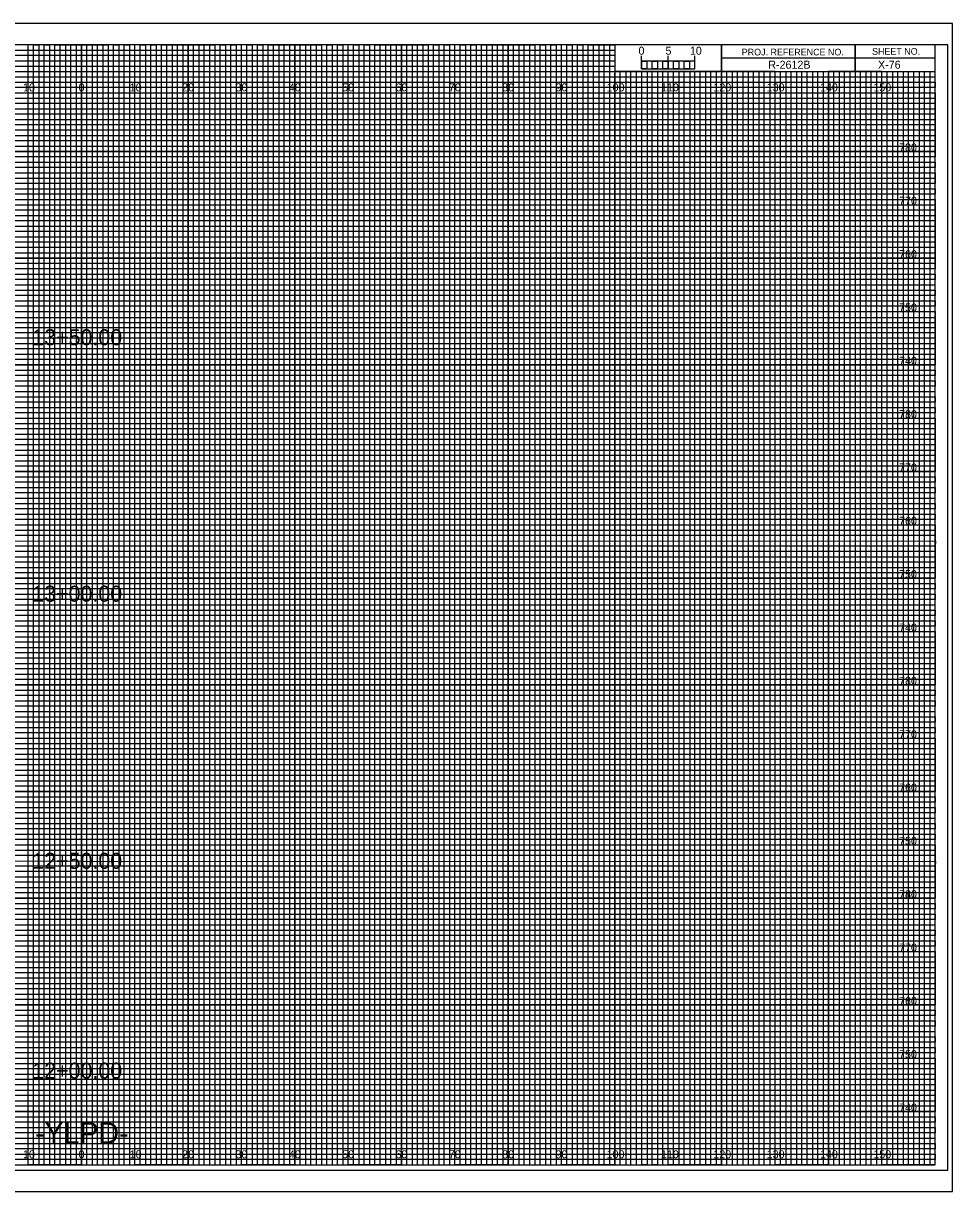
# Model space of a CAD drawing. Extents: x -13 to 323, y 215 to 434.
# Drawn here: x 149.1 to 323.3, y 215 to 434 of the extents above; entities that cross this region are included whole.
import ezdxf

# ---------------------------------------------------------------- set-up
doc = ezdxf.new("R2010")
doc.units = 0
for name, color, linetype in [('Prop XS Alignment Label', 7, 'Continuous'), ('Prop XS Bar Scale Labels', 7, 'Continuous'), ('Prop XS Elevation Labels', 7, 'Continuous'), ('Prop XS Offset Labels', 7, 'Continuous'), ('Prop XS Project Number', 7, 'Continuous'), ('Prop XS Sheet Number', 7, 'Continuous'), ('Prop XS Station Labels', 7, 'Continuous'), ('Sheet Cross Section CELL', 7, 'Continuous'), ('Sheet Cross Section Grid Major CELL', 7, 'Continuous'), ('Sheet Cross Section Grid Middle CELL', 7, 'Continuous'), ('Sheet Cross Section Grid Minor 1 CELL', 7, 'Continuous'), ('Sheet Cross Section Grid Minor 2 CELL', 7, 'Continuous'), ('Sheet Cross Section Scale CELL', 7, 'Continuous'), ('Sheet Cutting Line CELL', 7, 'Continuous'), ('Sheet DOT Grid CELL', 7, 'Continuous'), ('Sheet Plot Border Inside CELL', 7, 'Continuous'), ('Sheet Plot Border Outside CELL', 7, 'Continuous')]:
    doc.layers.add(name, color=color, linetype=linetype)

msp = doc.modelspace()

# ---------------------------------------------------------------- linework, layer by layer
at = {"layer": 'Sheet Cross Section CELL'}
for p, q in [((305, 430), (305, 425)), ((305, 425), (305, 430)), ((280, 427.5), (280, 425)), ((320, 427.49), (280, 427.49)), ((280, 425), (320, 425))]:
    msp.add_line(p, q, dxfattribs=at)
for points in [[(320, 430), (0, 430), (0, 220), (320, 220)], [(280, 430), (260, 430), (260, 425.03), (280, 425.03)], [(320, 430), (280, 430), (280, 425), (320, 425)]]:
    msp.add_lwpolyline(points, close=True, dxfattribs=at)
at = {"layer": 'Sheet Cross Section Grid Major CELL'}
for p, q in [((150, 430), (140, 430)), ((150, 220), (150, 430)), ((170, 430), (160, 430)), ((160, 430), (160, 220)), ((170, 220), (170, 430)), ((190, 430), (180, 430)), ((180, 430), (180, 220)), ((190, 220), (190, 430)), ((210, 430), (200, 430)), ((200, 430), (200, 220)), ((210, 220), (210, 430)), ((230, 430), (220, 430)), ((220, 430), (220, 220)), ((230, 220), (230, 430)), ((250, 430), (240, 430)), ((240, 430), (240, 220)), ((250, 220), (250, 430)), ((260, 430), (260, 220)), ((270, 220), (270, 425)), ((290, 425), (280, 425)), ((280, 425), (280, 220)), ((290, 220), (290, 425)), ((310, 425), (300, 425)), ((300, 425), (300, 220)), ((310, 220), (310, 425)), ((160, 220), (150, 220)), ((180, 220), (170, 220)), ((200, 220), (190, 220)), ((220, 220), (210, 220)), ((240, 220), (230, 220)), ((260, 220), (250, 220)), ((280, 220), (270, 220)), ((300, 220), (290, 220)), ((320, 220), (310, 220)), ((320, 220), (320, 220))]:
    msp.add_line(p, q, dxfattribs=at)
for points in [[(0, 420), (320, 420), (320, 410), (0, 410)], [(0, 400), (320, 400), (320, 390), (0, 390)], [(0, 380), (320, 380), (320, 370), (0, 370)], [(0, 360), (320, 360), (320, 350), (0, 350)], [(0, 340), (320, 340), (320, 330), (0, 330)], [(0, 320), (320, 320), (320, 310), (0, 310)], [(0, 300), (320, 300), (320, 290), (0, 290)], [(0, 280), (320, 280), (320, 270), (0, 270)], [(0, 260), (320, 260), (320, 250), (0, 250)], [(0, 240), (320, 240), (320, 230), (0, 230)]]:
    msp.add_lwpolyline(points, dxfattribs=at)
at = {"layer": 'Sheet Cross Section Grid Middle CELL'}
for points in [[(145, 220), (155, 220), (155, 430), (165, 430), (165, 220), (175, 220), (175, 430), (185, 430), (185, 220), (195, 220), (195, 430), (205, 430), (205, 220), (215, 220), (215, 430), (225, 430), (225, 220), (235, 220), (235, 430), (245, 430), (245, 220), (255, 220), (255, 430), (259.93, 430), (260, 430), (260, 425), (264.99, 425), (264.99, 220), (275, 220), (275, 425), (285, 425), (285, 220), (295, 220), (295, 425), (305, 425), (305, 220), (315, 220), (315, 425)], [(0, 425), (275, 425)], [(0, 405), (320, 405), (320, 415), (0, 415)], [(0, 385), (320, 385), (320, 395), (0, 395)], [(0, 365), (320, 365), (320, 375), (0, 375)], [(0, 345), (320, 345), (320, 355), (0, 355)], [(0, 325), (320, 325), (320, 335), (0, 335)], [(0, 305), (320, 305), (320, 315), (0, 315)], [(0, 285), (320, 285), (320, 295), (0, 295)], [(0, 265), (320, 265), (320, 275), (0, 275)], [(0, 245), (320, 245), (320, 255), (0, 255)], [(0, 225), (320, 225), (320, 235), (0, 235)]]:
    msp.add_lwpolyline(points, dxfattribs=at)
at = {"layer": 'Sheet Cross Section Grid Minor 1 CELL'}
for p, q in [((0, 429), (260, 429)), ((260, 427.98), (0, 427.98)), ((260, 429), (260, 427.98)), ((0, 427), (260, 427)), ((260, 425.89), (0, 425.89)), ((260, 427), (260, 425.89)), ((0, 424), (320, 424))]:
    msp.add_line(p, q, dxfattribs=at)
for points in [[(0, 423), (270, 423), (320, 423), (320, 422), (0, 422)], [(0, 421), (320, 421), (320, 419), (0, 419)], [(0, 418), (320, 418), (320, 417), (0, 416.98)], [(0, 416), (320, 416), (320, 414), (0, 414)], [(0, 413), (320, 413), (320, 412), (0, 412)], [(0, 411), (320, 411), (320, 409), (0, 409)], [(0, 408), (320, 408), (320, 407), (0, 407)], [(0, 406), (320, 406), (320, 404), (0, 404)], [(0, 403), (320, 403), (320, 402), (0, 402)], [(0, 401), (320, 401), (320, 399), (0, 399)], [(0, 398), (320, 398), (320, 397), (0, 397)], [(0, 396), (320, 396), (320, 393.95), (320, 393), (320, 392), (0, 392)], [(0, 394), (320, 394), (320, 393), (0, 393)], [(0, 391), (320, 391), (320, 389), (0, 389.03)], [(0, 389.03), (320, 389), (320, 388), (0, 388)], [(0, 387), (320, 387), (320, 386), (0, 386)], [(0, 384), (320, 384), (320, 383), (0, 383)], [(0, 382), (320, 382), (320, 381), (0, 381)], [(-0.07, 378.89), (320, 378.89), (320, 377.88), (-0.07, 377.88)], [(0, 377), (320, 377), (320, 376), (0, 376)], [(0, 374), (320, 374), (320, 373), (0, 373)], [(0, 372), (320, 372), (320, 371), (0, 371)], [(0, 369), (320, 369), (320, 368), (0, 368)], [(0, 367), (320, 367), (320, 366), (0, 366)], [(0, 364), (320, 364), (320, 363), (0, 363)], [(0, 362), (320, 362), (320, 361), (0, 361)], [(0, 359), (320, 359), (319.99, 357.98), (0, 358)], [(0, 357), (320, 357), (320, 356), (0, 356)], [(0, 354), (320, 354), (320, 353), (0, 353)], [(0, 352), (320, 352), (320, 351), (0, 351)], [(0, 349), (320, 349), (320, 348), (0, 348)], [(0, 347), (320, 347), (320, 346), (0, 346)], [(0, 344), (320, 344), (320, 343), (0, 343)], [(0, 342), (320, 342), (320, 341), (0, 341)], [(0, 339), (320, 339), (320, 338), (0, 338)], [(0, 336.99), (320.07, 336.91), (320, 336), (0, 336)], [(0, 334), (320, 334), (320, 333), (0, 333)], [(0, 332), (320, 332), (320, 331), (0, 331)], [(0, 329), (320, 329), (320, 328), (0, 328)], [(0, 327), (320, 327), (320, 326), (0, 326)], [(0, 324), (320, 324), (320, 323), (0, 323)], [(0, 322), (320, 322), (320, 321), (0, 321)], [(0, 319), (320, 319), (320, 318), (0, 318)], [(0, 317), (320, 317), (320, 316), (0, 316)], [(0, 314), (320, 314), (320, 313), (0, 313)], [(0, 312), (320, 312), (320, 311), (0, 311)], [(0, 309), (320, 309), (320, 308), (0, 308)], [(0, 307), (320, 307), (320, 306), (0, 306)], [(0, 304), (320, 304), (320, 303), (0, 303)], [(0, 302), (320, 302), (320, 301), (0, 301)], [(0, 299), (320, 299), (319.99, 297.98), (0, 298)], [(0, 297), (320, 297), (320, 296), (0, 296)], [(0, 294), (320, 294), (320, 293), (0, 293)], [(0, 292), (320, 292), (320, 291), (0, 291)], [(0, 289), (320, 289), (320, 288), (0, 288)], [(0, 287), (320, 287), (320, 286), (0, 286)], [(0, 284), (320, 284), (320, 283), (0, 283)], [(0, 282), (320, 282), (320, 281), (0, 281)], [(0, 279), (320, 279), (320, 278), (0, 278)], [(0, 276.99), (320.07, 276.91), (320, 276), (0, 276)], [(0, 274), (320, 274), (320, 273), (0, 273)], [(0, 272), (320, 272), (320, 271), (0, 271)], [(0, 269), (320, 269), (320, 268), (0, 268)], [(0, 267), (320, 267), (320, 266), (0, 266)], [(0, 264), (320, 264), (320, 263), (0, 263)], [(0, 262), (320, 262), (320, 261), (0, 261)], [(0, 259), (320, 259), (320, 258), (0, 258)], [(0, 257), (320, 257), (320, 256), (0, 256)], [(0, 254), (320, 254), (320, 253), (0, 253)], [(0, 252), (320, 252), (320, 251), (0, 251)], [(0, 249), (320, 249), (320, 248), (0, 248)], [(0, 247), (320, 247), (320, 246), (0, 246)], [(0, 244), (320, 244), (320, 243), (0, 243)], [(0, 242), (320, 242), (320, 241), (0, 241)], [(0, 239), (320, 239), (320, 238), (0, 238)], [(0, 237), (320, 237), (320, 236), (0, 236)], [(0, 234), (320, 234), (320, 233), (0, 233)], [(0, 232), (320, 232), (320, 231), (0, 231)], [(0, 229), (320, 229), (320, 228), (0, 228)], [(0, 227), (320, 227), (320, 226), (0, 226)], [(0, 224), (320, 224), (320, 223), (0, 223)], [(0, 222), (320, 222), (320, 221), (0, 221)]]:
    msp.add_lwpolyline(points, dxfattribs=at)
at = {"layer": 'Sheet Cross Section Grid Minor 2 CELL'}
for p, q in [((267, 425), (266.01, 425)), ((266.01, 425), (266.01, 220)), ((267, 220), (267, 425)), ((269, 425), (268, 425)), ((268, 425), (268, 220)), ((269, 220), (269, 425)), ((266.01, 220), (265, 220)), ((268, 220), (267, 220))]:
    msp.add_line(p, q, dxfattribs=at)
for points in [[(150, 220), (151, 220), (151, 430), (152, 430), (152, 220)], [(152, 220), (153, 220), (153, 430), (154, 430), (154, 220)], [(155, 220), (156, 220), (156, 430), (157, 430), (157, 220)], [(157, 220), (158, 220), (158, 430), (159, 430), (159, 220)], [(160, 220), (161, 220), (161, 430), (162, 430), (162, 220)], [(162, 220), (163, 220), (163, 430), (164, 430), (164, 220)], [(165, 220), (166, 220), (166, 430), (167, 430), (167, 220)], [(167, 220), (168, 220), (168, 430), (169, 430), (169, 220)], [(170, 220), (171, 220), (171, 430), (172, 430), (172, 220)], [(172, 220), (173, 220), (173, 430), (174, 430), (174, 220)], [(175, 220), (176, 220), (176, 430), (177, 430), (177, 220)], [(177, 220), (178, 220), (178, 430), (179, 430), (179, 220)], [(180, 220), (181, 220), (181, 430), (182, 430), (182, 220)], [(182, 220), (183, 220), (183, 430), (184, 430), (184, 220)], [(185, 220), (186, 220), (186, 430), (187, 430), (187, 220)], [(187, 220), (188, 220), (188, 430), (189, 430), (189, 220)], [(190, 220), (191, 220), (191, 430), (192, 430), (192, 220)], [(192, 220), (193, 220), (193, 430), (194, 430), (194, 220)], [(195, 220), (196, 220), (196, 430), (197, 430), (197, 220)], [(197, 220), (198, 220), (198, 430), (199, 430), (199, 220)], [(200, 220), (201, 220), (201, 430), (202, 430), (202, 220)], [(202, 220), (203, 220), (203, 430), (204, 430), (204, 220)], [(205, 220), (206, 220), (206, 430), (207, 430), (207, 220)], [(207, 220), (208, 220), (208, 430), (209, 430), (209, 220)], [(210, 220), (211, 220), (211, 430), (212, 430), (212, 220)], [(212, 220), (213, 220), (213, 430), (214, 430), (214, 220)], [(215, 220), (216, 220), (216, 430), (217, 430), (217, 220)], [(217, 220), (218, 220), (218, 430), (219, 430), (219, 220)], [(220, 220), (221, 220), (221, 430), (222, 430), (222, 220)], [(222, 220), (223, 220), (223, 430), (224, 430), (224, 220)], [(225, 220), (226, 220), (226, 430), (227, 430), (227, 220)], [(227, 220), (228, 220), (228, 430), (229, 430), (229, 220)], [(230, 220), (231, 220), (231, 430), (232, 430), (232, 220)], [(232, 220), (233, 220), (233, 430), (234, 430), (234, 220)], [(235, 220), (236, 220), (236, 430), (237, 430), (237, 220)], [(237, 220), (238, 220), (238, 430), (239, 430), (239, 220)], [(240, 220), (241, 220), (241, 430), (242, 430), (242, 220)], [(242, 220), (243, 220), (243, 430), (244, 430), (244, 220)], [(245, 220), (246, 220), (246, 430), (247, 430), (247, 220)], [(247, 220), (248, 220), (248, 430), (249, 430), (249, 220)], [(250, 220), (251, 220), (251, 430), (252, 430), (252, 220)], [(252, 220), (253, 220), (253, 430), (254, 430), (254, 220)], [(255, 220), (256, 220), (256, 430), (257, 430), (257, 220)], [(257, 220), (258, 220), (258, 430), (259, 430), (259, 220)], [(260, 220), (261, 220), (261, 425), (262.02, 425), (262.02, 220)], [(262, 220), (263, 220), (263, 425), (263.99, 425), (263.99, 220)], [(270, 220), (270.98, 220), (270.98, 425), (272, 425), (272, 220)], [(272, 220), (273, 220), (273, 425), (274.05, 425), (274.05, 220)], [(275, 220), (276, 220), (276, 425), (277, 425), (277, 220)], [(277, 220), (278, 220), (278, 425), (279, 425), (279, 220)], [(280, 220), (281, 220), (281, 425), (282, 425), (282, 220)], [(282, 220), (283, 220), (283, 425), (284, 425), (284, 220)], [(285, 220), (286, 220), (286, 425), (287, 425), (287, 220)], [(287, 220), (288, 220), (288, 425), (289, 425), (289, 220)], [(290, 220), (291, 220), (291, 425), (292, 425), (292, 220)], [(292, 220), (293, 220), (293, 425), (294, 425), (294, 220)], [(295, 220), (296, 220), (296, 425), (297, 425), (297, 220)], [(297, 220), (298, 220), (298, 425), (299, 425), (299, 220)], [(300, 220), (301, 220), (301, 425), (302, 425), (302, 220)], [(302, 220), (303, 220), (303, 425), (304, 425), (304, 220)], [(305, 220), (306, 220), (306, 425), (307, 425), (307, 220)], [(307, 220), (308, 220), (308, 425), (309, 425), (309, 220)], [(310, 220), (311, 220), (311, 425), (312, 425), (312, 220)], [(312, 220), (313, 220), (313, 425), (314, 425), (314, 220)], [(315, 220), (316, 220), (316, 425), (317, 425), (317, 220)], [(317, 220), (318, 220), (318, 425), (319, 425), (319, 220)]]:
    msp.add_lwpolyline(points, dxfattribs=at)
at = {"layer": 'Sheet Cross Section Scale CELL'}
for p, q in [((265, 425.49), (265, 427.9)), ((265, 426.9), (265, 427.9)), ((270, 425.49), (270, 427.9)), ((275, 425.49), (275, 427.9)), ((275, 426.9), (275, 427.9))]:
    msp.add_line(p, q, dxfattribs=at)
for points in [[(275, 426.9), (265, 426.9), (265, 425.49), (275, 425.49)], [(265, 426.9), (266, 426.9), (266, 425.49), (265, 425.49)], [(267, 426.9), (268, 426.9), (268, 425.49), (267, 425.49)], [(269, 426.9), (270, 426.9), (270, 425.49), (269, 425.49)], [(271, 426.9), (272, 426.9), (272, 425.49), (271, 425.49)], [(273, 426.9), (274, 426.9), (274, 425.49), (273, 425.49)]]:
    msp.add_lwpolyline(points, close=True, dxfattribs=at)
at = {"layer": 'Sheet Cutting Line CELL'}
for p, q in [((323.3, 434), (-13.4, 434)), ((-13.4, 215), (323.3, 215))]:
    msp.add_line(p, q, dxfattribs=at)
at = {"layer": 'Sheet DOT Grid CELL'}
for p, q in [((150, 220), (150, 430)), ((160, 220), (160, 430)), ((170, 220), (170, 430)), ((180, 220), (180, 430)), ((190, 220), (190, 430)), ((200, 220), (200, 430)), ((210, 220), (210, 430)), ((220, 220), (220, 430)), ((230, 220), (230, 430)), ((240, 220), (240, 430)), ((250, 220), (250, 430)), ((260, 220), (260, 424.69)), ((270, 220), (270, 424.69)), ((280, 220), (280, 424.69)), ((290, 220), (290, 424.69)), ((300, 220), (300, 424.69)), ((310, 220), (310, 424.69)), ((0, 420), (320, 420)), ((0, 410), (320, 410)), ((0, 400), (320, 400)), ((0, 390), (320, 390)), ((0, 380), (320, 380)), ((0, 370), (320, 370)), ((0, 360), (320, 360)), ((0, 350), (320, 350)), ((0, 340), (320, 340)), ((0, 330), (320, 330)), ((0, 320), (320, 320)), ((0, 310), (320, 310)), ((0, 300), (320, 300)), ((0, 290), (320, 290)), ((0, 280), (320, 280)), ((0, 270), (320, 270)), ((0, 260), (320, 260)), ((0, 250), (320, 250)), ((0, 240), (320, 240)), ((0, 230), (320, 230))]:
    msp.add_line(p, q, dxfattribs=at)
at = {"layer": 'Sheet Plot Border Inside CELL'}
msp.add_lwpolyline([(-10.8, 219), (322.4, 219), (322.4, 430), (-10.8, 430)], close=True, dxfattribs=at)
at = {"layer": 'Sheet Plot Border Outside CELL'}
msp.add_lwpolyline([(-13.4, 215), (323.3, 215), (323.3, 434), (-13.4, 434)], close=True, dxfattribs=at)

# ---------------------------------------------------------------- texts
at = {"layer": 'Prop XS Alignment Label'}
msp.add_text('-YLPD-', height=4, dxfattribs=at).set_placement((151.27, 224))
at = {"layer": 'Prop XS Bar Scale Labels'}
for s, p in [('5', (269.47, 428.12)), ('10', (274.04, 428.12))]:
    msp.add_text(s, height=1.5, dxfattribs=at).set_placement(p)
at = {"layer": 'Prop XS Elevation Labels'}
for s, p in [('780', (313.26, 410)), ('770', (313.26, 400)), ('760', (313.26, 390)), ('750', (313.26, 380)), ('740', (313.26, 370)), ('780', (313.26, 360)), ('770', (313.26, 350)), ('760', (313.26, 340)), ('750', (313.26, 330)), ('740', (313.26, 320)), ('780', (313.26, 310)), ('770', (313.26, 300)), ('760', (313.26, 290)), ('750', (313.26, 280)), ('780', (313.26, 270)), ('740', (313.26, 270)), ('770', (313.26, 260)), ('760', (313.26, 250)), ('750', (313.26, 240)), ('740', (313.26, 230))]:
    msp.add_text(s, height=1.5, dxfattribs=at).set_placement(p)
at = {"layer": 'Prop XS Offset Labels'}
for s, p in [('10', (149.04, 421.25)), ('0', (159.45, 421.25)), ('0', (159.45, 421.25)), ('10', (169.04, 421.25)), ('20', (178.86, 421.25)), ('30', (188.86, 421.25)), ('40', (198.86, 421.25)), ('50', (208.86, 421.25)), ('60', (218.86, 421.25)), ('70', (228.86, 421.25)), ('80', (238.86, 421.25)), ('90', (248.86, 421.25)), ('100', (258.44, 421.25)), ('110', (268.62, 421.25)), ('120', (278.44, 421.25)), ('130', (288.44, 421.25)), ('140', (298.44, 421.25)), ('150', (308.44, 421.25)), ('10', (149.04, 221.25)), ('0', (159.45, 221.25)), ('0', (159.45, 221.25)), ('10', (169.04, 221.25)), ('20', (178.86, 221.25)), ('30', (188.86, 221.25)), ('40', (198.86, 221.25)), ('50', (208.86, 221.25)), ('60', (218.86, 221.25)), ('70', (228.86, 221.25)), ('80', (238.86, 221.25)), ('90', (248.86, 221.25)), ('100', (258.44, 221.25)), ('110', (268.62, 221.25)), ('120', (278.44, 221.25)), ('130', (288.44, 221.25)), ('140', (298.44, 221.25)), ('150', (308.44, 221.25))]:
    msp.add_text(s, height=1.5, dxfattribs=at).set_placement(p)
at = {"layer": 'Prop XS Project Number'}
msp.add_text('R-2612B', height=1.5, dxfattribs=at).set_placement((288.74, 425.5))
at = {"layer": 'Prop XS Sheet Number'}
msp.add_text('X-76', height=1.5, dxfattribs=at).set_placement((309.31, 425.5))
at = {"layer": 'Prop XS Station Labels'}
for s, p in [('13+50.00', (150.77, 373.66)), ('13+00.00', (150.77, 325.59)), ('12+50.00', (150.77, 275.52)), ('12+00.00', (150.77, 236.18))]:
    msp.add_text(s, height=3, dxfattribs=at).set_placement(p)
at = {"layer": 'Sheet Cross Section CELL'}
for s, p in [('PROJ. REFERENCE NO.', (283.77, 427.99)), ('SHEET NO.', (308.19, 428.12))]:
    msp.add_text(s, height=1.25, dxfattribs=at).set_placement(p)
at = {"layer": 'Sheet Cross Section Scale CELL'}
msp.add_text('0', height=1.5, dxfattribs=at).set_placement((264.41, 428.12))

doc.saveas('drawing.dxf')
